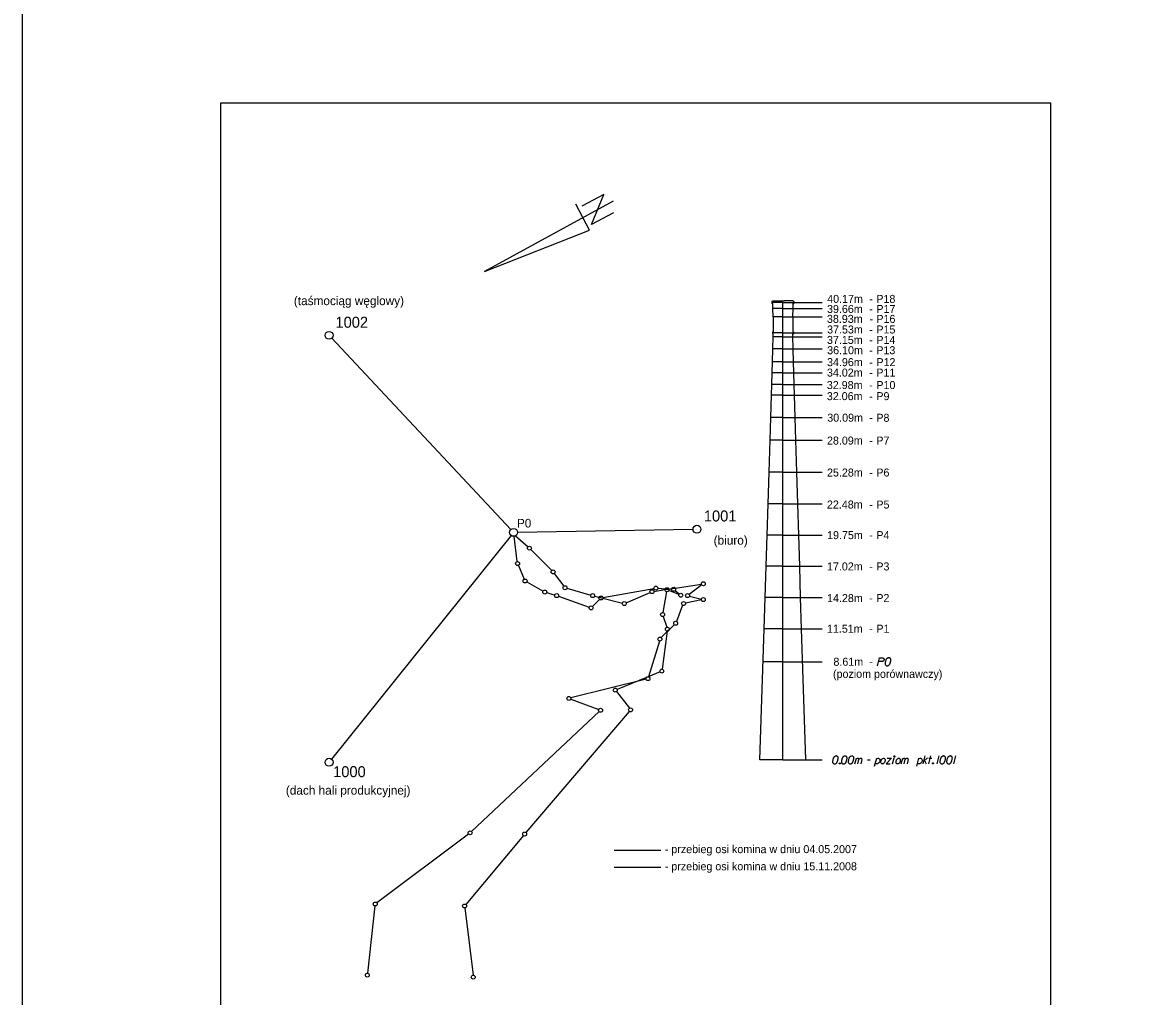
# Model space of a CAD drawing. Extents: x 138 to 264, y -75 to 121.
# Drawn here: x 137.94 to 166.54, y -56.31 to -31.68 of the extents above; entities that cross this region are included whole.
import ezdxf

# ---------------------------------------------------------------- set-up
doc = ezdxf.new("R2010")
doc.units = 0
for name, color, linetype in [('15 listopad 2008', 7, 'Continuous'), ('Opisy', 7, 'Continuous'), ('Ramka do drukowania', 7, 'Continuous'), ('Standart wykresów', 7, 'Continuous'), ('Wykresy 15 listopad 2008', 7, 'Continuous'), ('Wykresy 4 maj 2008', 7, 'Continuous')]:
    doc.layers.add(name, color=color, linetype=linetype)

msp = doc.modelspace()

# ---------------------------------------------------------------- linework, layer by layer
at = {"layer": '15 listopad 2008'}
for p, q in [((152.902, -52.613), (154.084, -52.613)), ((152.902, -53.045), (154.084, -53.045))]:
    msp.add_line(p, q, dxfattribs=at)
msp.add_lwpolyline([(137.936, 38.661), (264.389, 38.661), (264.389, -75.347), (137.936, -75.347)], close=True, dxfattribs=at)
at = {"layer": 'Opisy'}
for p, q in [((156.89, -38.741), (156.89, -38.765)), ((156.912, -38.741), (156.89, -38.741)), ((157.169, -38.765), (156.89, -38.765)), ((156.89, -38.765), (156.89, -38.79)), ((156.912, -38.79), (156.89, -38.79)), ((156.912, -38.717), (156.912, -38.741)), ((156.912, -38.717), (157.21, -38.717)), ((156.912, -38.913), (156.912, -38.79)), ((157.169, -50.331), (157.169, -38.717)), ((157.169, -38.765), (158.158, -38.765)), ((157.427, -38.717), (157.21, -38.717)), ((157.427, -38.717), (157.427, -38.741)), ((157.427, -38.741), (157.449, -38.741)), ((157.427, -38.79), (157.449, -38.79)), ((157.427, -38.913), (157.427, -38.79)), ((157.449, -38.741), (157.449, -38.765)), ((157.449, -38.765), (157.449, -38.79)), ((157.169, -38.913), (156.912, -38.913)), ((156.92, -39.123), (156.912, -38.913)), ((157.169, -39.123), (156.92, -39.123)), ((156.92, -39.123), (156.92, -39.501)), ((157.169, -38.913), (158.158, -38.913)), ((157.169, -39.123), (158.158, -39.123)), ((157.418, -39.123), (157.427, -38.913)), ((157.418, -39.123), (157.418, -39.501)), ((156.903, -39.501), (156.903, -39.527)), ((156.903, -39.501), (156.92, -39.501)), ((157.169, -39.527), (156.903, -39.527)), ((156.903, -39.527), (156.903, -39.552)), ((156.923, -39.552), (156.903, -39.552)), ((156.912, -39.939), (156.92, -39.635)), ((156.92, -39.635), (156.923, -39.552)), ((157.169, -39.635), (156.92, -39.635)), ((157.169, -39.527), (158.158, -39.527)), ((157.169, -39.635), (158.158, -39.635)), ((157.418, -39.635), (157.416, -39.552)), ((157.416, -39.552), (157.436, -39.552)), ((157.436, -39.501), (157.418, -39.501)), ((157.427, -39.939), (157.418, -39.635)), ((157.436, -39.501), (157.436, -39.527)), ((157.436, -39.527), (157.436, -39.552)), ((156.903, -40.268), (156.912, -39.939)), ((157.169, -39.939), (156.912, -39.939)), ((157.169, -39.939), (158.158, -39.939)), ((157.436, -40.268), (157.427, -39.939)), ((156.895, -40.538), (156.903, -40.268)), ((157.169, -40.268), (156.903, -40.268)), ((157.169, -40.268), (158.158, -40.268)), ((157.444, -40.538), (157.436, -40.268)), ((156.887, -40.837), (156.895, -40.538)), ((157.169, -40.538), (156.895, -40.538)), ((157.169, -40.538), (158.158, -40.538)), ((157.452, -40.837), (157.444, -40.538)), ((156.877, -41.103), (156.887, -40.837)), ((157.169, -40.837), (156.887, -40.837)), ((157.169, -40.837), (158.158, -40.837)), ((157.462, -41.103), (157.452, -40.837)), ((156.861, -41.67), (156.877, -41.103)), ((157.169, -41.103), (156.877, -41.103)), ((157.169, -41.103), (158.158, -41.103)), ((157.477, -41.67), (157.462, -41.103)), ((156.844, -42.244), (156.861, -41.67)), ((157.169, -41.67), (156.861, -41.67)), ((157.169, -41.67), (158.158, -41.67)), ((157.495, -42.244), (157.477, -41.67)), ((156.821, -43.055), (156.844, -42.244)), ((157.169, -42.244), (156.844, -42.244)), ((157.169, -42.244), (158.158, -42.244)), ((157.518, -43.055), (157.495, -42.244)), ((156.795, -43.859), (156.821, -43.055)), ((157.169, -43.055), (156.821, -43.055)), ((157.169, -43.055), (158.158, -43.055)), ((157.544, -43.859), (157.518, -43.055)), ((156.771, -44.645), (156.795, -43.859)), ((157.169, -43.859), (156.795, -43.859)), ((157.169, -43.859), (158.158, -43.859)), ((157.568, -44.645), (157.544, -43.859)), ((156.746, -45.431), (156.771, -44.645)), ((157.169, -44.645), (156.771, -44.645)), ((157.169, -44.645), (158.158, -44.645)), ((157.593, -45.431), (157.568, -44.645)), ((156.722, -46.221), (156.746, -45.431)), ((157.169, -45.431), (156.746, -45.431)), ((157.169, -45.431), (158.158, -45.431)), ((157.617, -46.221), (157.593, -45.431)), ((156.696, -47.017), (156.722, -46.221)), ((157.169, -46.221), (156.722, -46.221)), ((157.169, -46.221), (158.158, -46.221)), ((157.643, -47.017), (157.617, -46.221)), ((156.587, -50.331), (156.696, -47.017)), ((157.169, -47.017), (156.696, -47.017)), ((157.169, -47.017), (158.158, -47.017)), ((157.751, -50.331), (157.643, -47.017)), ((157.169, -47.853), (156.669, -47.853)), ((157.169, -47.853), (158.158, -47.853)), ((157.169, -50.331), (156.587, -50.331)), ((157.169, -50.331), (158.158, -50.331))]:
    msp.add_line(p, q, dxfattribs=at)
for points in [[(159.562, -47.951), (159.616, -47.749), (159.685, -47.749), (159.694, -47.75), (159.699, -47.752), (159.708, -47.756), (159.715, -47.761), (159.72, -47.768), (159.724, -47.776), (159.728, -47.787), (159.729, -47.796), (159.728, -47.804), (159.726, -47.811), (159.723, -47.817), (159.72, -47.822), (159.715, -47.828), (159.708, -47.833), (159.704, -47.836), (159.696, -47.839), (159.688, -47.841), (159.592, -47.841)], [(159.852, -47.749), (159.849, -47.749), (159.839, -47.75), (159.833, -47.752), (159.828, -47.753), (159.82, -47.756), (159.81, -47.761), (159.802, -47.766), (159.795, -47.772), (159.79, -47.779), (159.785, -47.787), (159.78, -47.795), (159.775, -47.804), (159.772, -47.811), (159.769, -47.82), (159.764, -47.836), (159.759, -47.86), (159.756, -47.879), (159.756, -47.897), (159.758, -47.909), (159.764, -47.924), (159.769, -47.932), (159.777, -47.941), (159.787, -47.948), (159.791, -47.949), (159.801, -47.951), (159.809, -47.951), (159.822, -47.949), (159.833, -47.946), (159.841, -47.941), (159.852, -47.933), (159.857, -47.929), (159.863, -47.922), (159.868, -47.916), (159.871, -47.911), (159.874, -47.903), (159.876, -47.9), (159.879, -47.892), (159.882, -47.882), (159.885, -47.873), (159.887, -47.866), (159.889, -47.862), (159.89, -47.855), (159.893, -47.841), (159.895, -47.833), (159.897, -47.825), (159.898, -47.814), (159.9, -47.799), (159.9, -47.795), (159.898, -47.788), (159.897, -47.782), (159.892, -47.772), (159.887, -47.766), (159.882, -47.761), (159.876, -47.756), (159.869, -47.753), (159.865, -47.752), (159.86, -47.75), (159.852, -47.749)], [(158.521, -50.233), (158.518, -50.233), (158.508, -50.235), (158.502, -50.236), (158.497, -50.238), (158.489, -50.241), (158.479, -50.246), (158.471, -50.251), (158.463, -50.257), (158.459, -50.263), (158.454, -50.271), (158.449, -50.279), (158.444, -50.289), (158.441, -50.295), (158.438, -50.305), (158.433, -50.321), (158.428, -50.345), (158.425, -50.364), (158.425, -50.381), (158.427, -50.394), (158.433, -50.408), (158.438, -50.416), (158.446, -50.426), (158.455, -50.432), (158.46, -50.434), (158.47, -50.435), (158.478, -50.435), (158.491, -50.434), (158.502, -50.431), (158.51, -50.426), (158.521, -50.418), (158.526, -50.413), (158.532, -50.407), (158.537, -50.4), (158.54, -50.396), (158.543, -50.388), (158.545, -50.384), (158.548, -50.376), (158.551, -50.367), (158.554, -50.357), (158.556, -50.351), (158.557, -50.346), (158.559, -50.34), (158.562, -50.325), (158.564, -50.318), (158.565, -50.31), (158.567, -50.298), (158.569, -50.284), (158.569, -50.279), (158.567, -50.273), (158.565, -50.267), (158.561, -50.257), (158.556, -50.251), (158.551, -50.246), (158.545, -50.241), (158.538, -50.238), (158.534, -50.236), (158.529, -50.235), (158.521, -50.233)], [(158.745, -50.233), (158.742, -50.233), (158.733, -50.235), (158.726, -50.236), (158.722, -50.238), (158.714, -50.241), (158.704, -50.246), (158.696, -50.251), (158.688, -50.257), (158.683, -50.263), (158.679, -50.271), (158.674, -50.279), (158.669, -50.289), (158.666, -50.295), (158.663, -50.305), (158.658, -50.321), (158.653, -50.345), (158.65, -50.364), (158.65, -50.381), (158.651, -50.394), (158.658, -50.408), (158.663, -50.416), (158.671, -50.426), (158.68, -50.432), (158.685, -50.434), (158.694, -50.435), (158.702, -50.435), (158.715, -50.434), (158.726, -50.431), (158.734, -50.426), (158.745, -50.418), (158.75, -50.413), (158.757, -50.407), (158.761, -50.4), (158.765, -50.396), (158.768, -50.388), (158.769, -50.384), (158.773, -50.376), (158.776, -50.367), (158.779, -50.357), (158.781, -50.351), (158.782, -50.346), (158.784, -50.34), (158.787, -50.325), (158.789, -50.318), (158.79, -50.31), (158.792, -50.298), (158.793, -50.284), (158.793, -50.279), (158.792, -50.273), (158.79, -50.267), (158.785, -50.257), (158.781, -50.251), (158.776, -50.246), (158.769, -50.241), (158.763, -50.238), (158.758, -50.236), (158.753, -50.235), (158.745, -50.233)], [(158.916, -50.233), (158.913, -50.233), (158.903, -50.235), (158.897, -50.236), (158.892, -50.238), (158.884, -50.241), (158.875, -50.246), (158.867, -50.251), (158.859, -50.257), (158.854, -50.263), (158.849, -50.271), (158.844, -50.279), (158.839, -50.289), (158.836, -50.295), (158.833, -50.305), (158.828, -50.321), (158.824, -50.345), (158.82, -50.364), (158.82, -50.381), (158.822, -50.394), (158.828, -50.408), (158.833, -50.416), (158.841, -50.426), (158.851, -50.432), (158.855, -50.434), (158.865, -50.435), (158.873, -50.435), (158.886, -50.434), (158.897, -50.431), (158.905, -50.426), (158.916, -50.418), (158.921, -50.413), (158.927, -50.407), (158.932, -50.4), (158.935, -50.396), (158.938, -50.388), (158.94, -50.384), (158.943, -50.376), (158.946, -50.367), (158.949, -50.357), (158.951, -50.351), (158.953, -50.346), (158.954, -50.34), (158.957, -50.325), (158.959, -50.318), (158.961, -50.31), (158.962, -50.298), (158.964, -50.284), (158.964, -50.279), (158.962, -50.273), (158.961, -50.267), (158.956, -50.257), (158.951, -50.251), (158.946, -50.246), (158.94, -50.241), (158.934, -50.238), (158.929, -50.236), (158.924, -50.235), (158.916, -50.233)], [(158.991, -50.435), (159.028, -50.29)], [(159.018, -50.329), (159.026, -50.311), (159.034, -50.302), (159.043, -50.295), (159.053, -50.29), (159.059, -50.287), (159.069, -50.287), (159.072, -50.289), (159.079, -50.295), (159.085, -50.303), (159.09, -50.318), (159.091, -50.325), (159.099, -50.311), (159.109, -50.302), (159.118, -50.295), (159.128, -50.29), (159.136, -50.287), (159.144, -50.287), (159.15, -50.289), (159.155, -50.295), (159.16, -50.303), (159.165, -50.318), (159.166, -50.325), (159.139, -50.435)], [(159.064, -50.435), (159.091, -50.325)], [(159.31, -50.333), (159.378, -50.333)], [(159.487, -50.488), (159.541, -50.289)], [(159.536, -50.306), (159.552, -50.294), (159.576, -50.289), (159.595, -50.292), (159.608, -50.302), (159.617, -50.314), (159.624, -50.332), (159.625, -50.348), (159.622, -50.362), (159.617, -50.38), (159.605, -50.399), (159.589, -50.416), (159.565, -50.432), (159.544, -50.435), (159.525, -50.434), (159.504, -50.423)], [(159.715, -50.289), (159.726, -50.289), (159.738, -50.295), (159.751, -50.313), (159.753, -50.321), (159.754, -50.329), (159.754, -50.335), (159.754, -50.359), (159.75, -50.375), (159.742, -50.394), (159.732, -50.41), (159.716, -50.424), (159.702, -50.435), (159.678, -50.435), (159.668, -50.432), (159.659, -50.424), (159.654, -50.416), (159.648, -50.397), (159.648, -50.369), (159.651, -50.359), (159.657, -50.338), (159.664, -50.327), (159.667, -50.321), (159.683, -50.303), (159.699, -50.294), (159.715, -50.289)], [(159.81, -50.286), (159.914, -50.286), (159.782, -50.435), (159.883, -50.435)], [(159.941, -50.435), (159.982, -50.281)], [(159.985, -50.233), (159.993, -50.233), (159.998, -50.236), (160.003, -50.243), (160.003, -50.251), (159.998, -50.257), (159.993, -50.26), (159.985, -50.26), (159.981, -50.257), (159.976, -50.251), (159.976, -50.243), (159.981, -50.236), (159.985, -50.233)], [(160.097, -50.289), (160.108, -50.289), (160.121, -50.295), (160.134, -50.313), (160.135, -50.321), (160.137, -50.329), (160.137, -50.335), (160.137, -50.359), (160.132, -50.375), (160.124, -50.394), (160.115, -50.41), (160.099, -50.424), (160.084, -50.435), (160.06, -50.435), (160.051, -50.432), (160.041, -50.424), (160.036, -50.416), (160.03, -50.397), (160.03, -50.369), (160.033, -50.359), (160.04, -50.338), (160.046, -50.327), (160.049, -50.321), (160.065, -50.303), (160.081, -50.294), (160.097, -50.289)], [(160.164, -50.435), (160.201, -50.29)], [(160.191, -50.329), (160.199, -50.311), (160.207, -50.302), (160.217, -50.295), (160.226, -50.29), (160.233, -50.287), (160.242, -50.287), (160.245, -50.289), (160.252, -50.295), (160.258, -50.303), (160.263, -50.318), (160.264, -50.325), (160.272, -50.311), (160.282, -50.302), (160.291, -50.295), (160.301, -50.29), (160.309, -50.287), (160.317, -50.287), (160.323, -50.289), (160.328, -50.295), (160.333, -50.303), (160.338, -50.318), (160.339, -50.325), (160.312, -50.435)], [(160.237, -50.435), (160.264, -50.325)], [(160.554, -50.488), (160.609, -50.289)], [(160.604, -50.306), (160.62, -50.294), (160.644, -50.289), (160.663, -50.292), (160.676, -50.302), (160.685, -50.314), (160.691, -50.332), (160.693, -50.348), (160.69, -50.362), (160.685, -50.38), (160.672, -50.399), (160.656, -50.416), (160.633, -50.432), (160.612, -50.435), (160.593, -50.434), (160.572, -50.423)], [(160.715, -50.435), (160.77, -50.233)], [(160.735, -50.364), (160.83, -50.284)], [(160.857, -50.435), (160.91, -50.233)], [(160.857, -50.289), (160.934, -50.289)], [(161.114, -50.233), (161.06, -50.435)], [(161.236, -50.233), (161.233, -50.233), (161.224, -50.235), (161.217, -50.236), (161.213, -50.238), (161.205, -50.241), (161.195, -50.246), (161.187, -50.251), (161.179, -50.257), (161.174, -50.263), (161.17, -50.271), (161.165, -50.279), (161.16, -50.289), (161.157, -50.295), (161.154, -50.305), (161.149, -50.321), (161.144, -50.345), (161.141, -50.364), (161.141, -50.381), (161.142, -50.394), (161.149, -50.408), (161.154, -50.416), (161.162, -50.426), (161.171, -50.432), (161.176, -50.434), (161.185, -50.435), (161.193, -50.435), (161.206, -50.434), (161.217, -50.431), (161.225, -50.426), (161.236, -50.418), (161.241, -50.413), (161.248, -50.407), (161.252, -50.4), (161.256, -50.396), (161.259, -50.388), (161.26, -50.384), (161.264, -50.376), (161.267, -50.367), (161.27, -50.357), (161.272, -50.351), (161.273, -50.346), (161.275, -50.34), (161.278, -50.325), (161.279, -50.318), (161.281, -50.31), (161.283, -50.298), (161.284, -50.284), (161.284, -50.279), (161.283, -50.273), (161.281, -50.267), (161.276, -50.257), (161.272, -50.251), (161.267, -50.246), (161.26, -50.241), (161.254, -50.238), (161.249, -50.236), (161.244, -50.235), (161.236, -50.233)], [(161.407, -50.233), (161.404, -50.233), (161.394, -50.235), (161.388, -50.236), (161.383, -50.238), (161.375, -50.241), (161.366, -50.246), (161.358, -50.251), (161.35, -50.257), (161.345, -50.263), (161.34, -50.271), (161.335, -50.279), (161.33, -50.289), (161.327, -50.295), (161.324, -50.305), (161.319, -50.321), (161.315, -50.345), (161.311, -50.364), (161.311, -50.381), (161.313, -50.394), (161.319, -50.408), (161.324, -50.416), (161.332, -50.426), (161.342, -50.432), (161.346, -50.434), (161.356, -50.435), (161.364, -50.435), (161.377, -50.434), (161.388, -50.431), (161.396, -50.426), (161.407, -50.418), (161.412, -50.413), (161.418, -50.407), (161.423, -50.4), (161.426, -50.396), (161.429, -50.388), (161.431, -50.384), (161.434, -50.376), (161.437, -50.367), (161.44, -50.357), (161.442, -50.351), (161.444, -50.346), (161.445, -50.34), (161.448, -50.325), (161.45, -50.318), (161.452, -50.31), (161.453, -50.298), (161.455, -50.284), (161.455, -50.279), (161.453, -50.273), (161.452, -50.267), (161.447, -50.257), (161.442, -50.251), (161.437, -50.246), (161.431, -50.241), (161.424, -50.238), (161.42, -50.236), (161.415, -50.235), (161.407, -50.233)], [(161.536, -50.233), (161.482, -50.435)], [(158.605, -50.408), (158.613, -50.408), (158.618, -50.412), (158.623, -50.418), (158.623, -50.426), (158.618, -50.432), (158.613, -50.435), (158.605, -50.435), (158.6, -50.432), (158.596, -50.426), (158.596, -50.418), (158.6, -50.412), (158.605, -50.408)], [(160.754, -50.348), (160.795, -50.435)], [(160.961, -50.408), (160.969, -50.408), (160.974, -50.412), (160.978, -50.418), (160.978, -50.426), (160.974, -50.432), (160.969, -50.435), (160.961, -50.435), (160.956, -50.432), (160.951, -50.426), (160.951, -50.418), (160.956, -50.412), (160.961, -50.408)]]:
    msp.add_lwpolyline(points, dxfattribs=at)
at = {"layer": 'Ramka do drukowania'}
for p, q in [((142.949, -63.414), (142.949, -33.714)), ((142.949, -33.714), (163.949, -33.714)), ((163.949, -63.414), (163.949, -33.714))]:
    msp.add_line(p, q, dxfattribs=at)
at = {"layer": 'Standart wykresów'}
for p, q in [((152.638, -36.028), (152.081, -36.324)), ((152.328, -36.788), (152.638, -36.028)), ((152.877, -36.196), (149.622, -37.977)), ((152.277, -36.932), (151.929, -36.274)), ((152.885, -36.491), (152.328, -36.788)), ((149.622, -37.977), (152.277, -36.932)), ((145.688, -39.593), (145.688, -39.593)), ((150.288, -44.504), (145.757, -39.666)), ((150.456, -44.575), (154.895, -44.5)), ((154.995, -44.498), (154.995, -44.498)), ((150.293, -44.655), (145.751, -50.313)), ((145.688, -50.391), (145.688, -50.391))]:
    msp.add_line(p, q, dxfattribs=at)
for centre in [(145.688, -39.593), (154.995, -44.498), (145.688, -50.391)]:
    msp.add_circle(centre, 0.1, dxfattribs=at)
at = {"layer": 'Wykresy 15 listopad 2008'}
for p, q in [((150.45, -45.317), (150.368, -44.676)), ((150.476, -45.413), (150.626, -45.761)), ((150.69, -45.831), (151.102, -46.062)), ((152.615, -46.228), (153.907, -45.996)), ((154.006, -45.99), (154.192, -46.003)), ((154.192, -46.003), (154.282, -46.009)), ((154.282, -46.009), (154.356, -46.013)), ((154.539, -46.148), (154.282, -46.045)), ((154.444, -46.049), (154.547, -46.135)), ((151.194, -46.101), (151.398, -46.162)), ((151.493, -46.194), (152.269, -46.47)), ((152.351, -46.451), (152.531, -46.272)), ((154.227, -46.076), (154.135, -46.607)), ((154.141, -46.704), (154.23, -46.979)), ((154.239, -47.076), (154.112, -48.037)), ((153.717, -48.245), (152.972, -48.548)), ((153.761, -48.227), (153.717, -48.245)), ((154.06, -48.106), (153.761, -48.227)), ((152.957, -48.606), (153.285, -49.027)), ((153.283, -49.105), (150.668, -52.169)), ((150.604, -52.245), (149.148, -53.988)), ((149.122, -54.076), (149.33, -55.777))]:
    msp.add_line(p, q, dxfattribs=at)
for centre, radius in [((150.356, -44.577), 0.1), ((150.456, -45.367), 0.05), ((150.646, -45.807), 0.05), ((151.146, -46.087), 0.05), ((153.956, -45.987), 0.05), ((154.236, -46.027), 0.05), ((154.406, -46.017), 0.05), ((151.446, -46.177), 0.05), ((152.566, -46.237), 0.05), ((154.586, -46.167), 0.05), ((152.316, -46.487), 0.05), ((154.126, -46.657), 0.05), ((154.246, -47.027), 0.05), ((154.106, -48.087), 0.05), ((152.926, -48.567), 0.05), ((153.316, -49.067), 0.05), ((150.636, -52.207), 0.05), ((149.116, -54.027), 0.05), ((149.336, -55.827), 0.05)]:
    msp.add_circle(centre, radius, dxfattribs=at)
at = {"layer": 'Wykresy 4 maj 2008'}
for p, q in [((150.407, -44.663), (150.721, -44.941)), ((150.791, -45.012), (151.321, -45.541)), ((151.386, -45.617), (151.626, -45.937)), ((151.704, -45.99), (152.308, -46.163)), ((153.905, -46.069), (154.186, -46.026)), ((154.186, -46.026), (154.283, -46.011)), ((154.283, -46.011), (154.359, -45.999)), ((154.359, -45.999), (154.445, -45.986)), ((154.445, -45.986), (155.106, -45.884)), ((155.116, -45.907), (154.796, -46.147)), ((152.404, -46.189), (152.52, -46.218)), ((152.52, -46.218), (152.616, -46.242)), ((152.616, -46.242), (153.107, -46.365)), ((153.202, -46.357), (153.81, -46.096)), ((155.107, -46.286), (154.704, -46.365)), ((154.803, -46.193), (155.107, -46.265)), ((154.63, -46.42), (154.474, -46.83)), ((154.42, -46.912), (154.296, -47.033)), ((154.251, -47.077), (154.086, -47.237)), ((154.296, -47.033), (154.251, -47.077)), ((154.043, -47.325), (153.77, -48.229)), ((153.707, -48.289), (151.804, -48.765)), ((151.803, -48.794), (152.509, -49.059)), ((152.519, -49.111), (149.292, -52.143)), ((149.216, -52.207), (146.895, -53.946)), ((146.848, -54.026), (146.661, -55.727))]:
    msp.add_line(p, q, dxfattribs=at)
for centre, radius in [((150.356, -44.577), 0.1), ((150.756, -44.977), 0.05), ((151.356, -45.577), 0.05), ((151.656, -45.977), 0.05), ((153.856, -46.077), 0.05), ((155.156, -45.877), 0.05), ((152.356, -46.177), 0.05), ((153.156, -46.377), 0.05), ((154.656, -46.377), 0.05), ((154.756, -46.177), 0.05), ((155.156, -46.277), 0.05), ((154.456, -46.877), 0.05), ((154.056, -47.277), 0.05), ((153.756, -48.277), 0.05), ((151.756, -48.777), 0.05), ((152.556, -49.077), 0.05), ((149.256, -52.177), 0.05), ((146.856, -53.977), 0.05), ((146.656, -55.777), 0.05)]:
    msp.add_circle(centre, radius, dxfattribs=at)

# ---------------------------------------------------------------- texts
at = {"layer": 'Opisy'}
for s, height, p in [('40.17m', 0.2024, (158.289, -38.773)), ('P18', 0.2024, (159.532, -38.773)), ('39.66m', 0.2024, (158.285, -39.028)), ('-', 0.202, (159.353, -38.773)), ('P17', 0.2024, (159.533, -39.028)), ('38.93m', 0.2024, (158.283, -39.279)), ('-', 0.202, (159.355, -39.028)), ('P16', 0.2024, (159.533, -39.279)), ('37.53m', 0.2024, (158.287, -39.547)), ('-', 0.202, (159.353, -39.547)), ('-', 0.202, (159.358, -39.279)), ('P15', 0.2024, (159.533, -39.547)), ('37.15m', 0.2024, (158.284, -39.811)), ('-', 0.202, (159.353, -39.811)), ('P14', 0.2024, (159.533, -39.811)), ('36.10m', 0.2024, (158.289, -40.071)), ('-', 0.202, (159.355, -40.071)), ('P13', 0.2024, (159.532, -40.071)), ('34.96m', 0.2024, (158.285, -40.373)), ('-', 0.202, (159.355, -40.373)), ('P12', 0.2024, (159.534, -40.373)), ('34.02m', 0.2024, (158.283, -40.637)), ('-', 0.202, (159.355, -40.637)), ('P11', 0.2024, (159.532, -40.637)), ('32.98m', 0.2024, (158.28, -40.952)), ('-', 0.202, (159.355, -40.952)), ('P10', 0.2024, (159.533, -40.952)), ('32.06m', 0.2024, (158.28, -41.233)), ('-', 0.202, (159.355, -41.233)), ('P9', 0.2024, (159.533, -41.233)), ('30.09m', 0.2024, (158.291, -41.778)), ('-', 0.202, (159.355, -41.778)), ('P8', 0.2024, (159.533, -41.78)), ('28.09m', 0.2024, (158.284, -42.356)), ('-', 0.202, (159.355, -42.356)), ('P7', 0.2024, (159.532, -42.356)), ('25.28m', 0.2024, (158.285, -43.165)), ('-', 0.202, (159.353, -43.165)), ('P6', 0.2024, (159.532, -43.165)), ('22.48m', 0.2024, (158.283, -43.974)), ('-', 0.202, (159.353, -43.974)), ('P5', 0.2024, (159.533, -43.974)), ('19.75m', 0.2024, (158.287, -44.748)), ('P4', 0.2024, (159.533, -44.748)), ('-', 0.202, (159.353, -44.748)), ('17.02m', 0.2024, (158.284, -45.54)), ('-', 0.202, (159.353, -45.54)), ('P3', 0.2024, (159.532, -45.54)), ('14.28m', 0.2024, (158.286, -46.34)), ('-', 0.202, (159.354, -46.34)), ('P2', 0.2024, (159.532, -46.34)), ('11.51m', 0.2024, (158.283, -47.115)), ('-', 0.202, (159.353, -47.115)), ('P1', 0.2024, (159.533, -47.115)), ('8.61m', 0.2024, (158.447, -47.951)), ('(poziom porównawczy)', 0.2024, (158.436, -48.258)), ('-', 0.202, (159.353, -47.951)), ('- przebieg osi komina w dniu 04.05.2007', 0.2024, (154.181, -52.691)), ('- przebieg osi komina w dniu 15.11.2008', 0.2024, (154.181, -53.125))]:
    msp.add_text(s, height=height, dxfattribs=at).set_placement(p)
at = {"layer": 'Standart wykresów'}
for s, height, p in [('(taśmociąg węglowy)', 0.22315, (144.798, -38.83)), ('1002', 0.2771, (145.85, -39.401)), ('1001', 0.2771, (155.169, -44.301)), ('(biuro)', 0.2231, (155.417, -44.887)), ('1000', 0.2771, (145.791, -50.768)), ('(dach hali produkcyjnej)', 0.22315, (144.595, -51.211))]:
    msp.add_text(s, height=height, dxfattribs=at).set_placement(p)
at = {"layer": 'Wykresy 4 maj 2008'}
msp.add_text('P0', height=0.22, dxfattribs=at).set_placement((150.444, -44.455))

doc.saveas('drawing.dxf')
